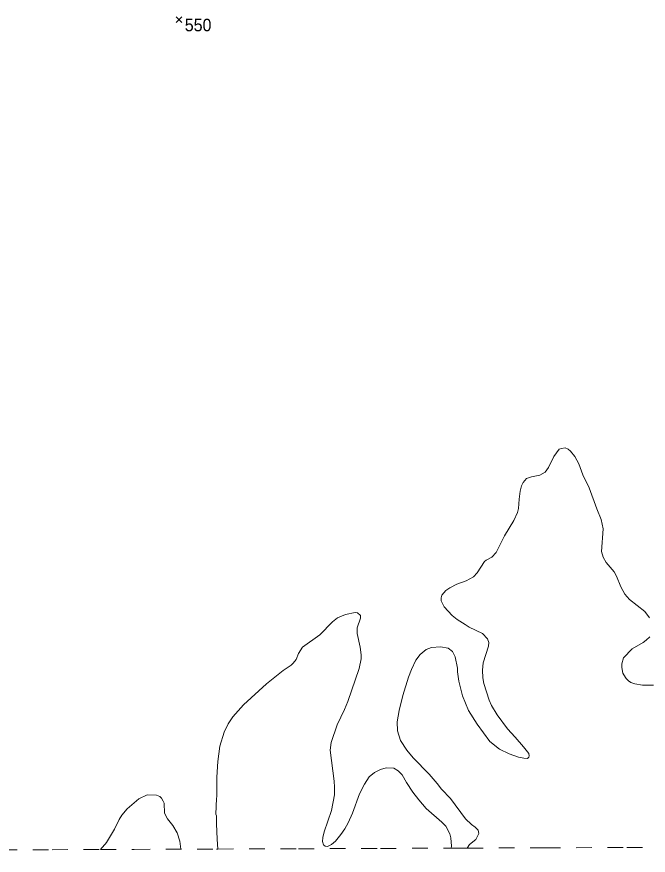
# Model space of a CAD drawing. Extents: x 423 to 448.8, y 7456.3 to 7484.
# Drawn here: x 439.12 to 443.14, y 7456.29 to 7461.63 of the extents above; entities that cross this region are included whole.
import ezdxf
from ezdxf.enums import TextEntityAlignment as Align

# ---------------------------------------------------------------- set-up
doc = ezdxf.new("R2010")
doc.units = 0
doc.header["$LTSCALE"] = 0.032
doc.linetypes.add('SHORT_DASHED', pattern=[2.7, 1.5, -1.2])
for name, color, linetype, lineweight in [('2', 7, 'Continuous', 13), ('21', 7, 'Continuous', 25), ('22', 7, 'SHORT_DASHED', 13)]:
    doc.layers.add(name, color=color, linetype=linetype, lineweight=lineweight)
doc.layers.add('61', color=7, linetype='Continuous')

msp = doc.modelspace()

# ---------------------------------------------------------------- linework, layer by layer
at = {"layer": '2'}
for points in [[(443.1494, 7457.8027), (443.1192, 7457.8422), (443.0202, 7457.9187), (442.9916, 7457.952), (442.9669, 7457.9984), (442.9383, 7458.0665), (442.9228, 7458.0943), (442.8725, 7458.1538), (442.8532, 7458.1887), (442.8439, 7458.2243), (442.8532, 7458.3681), (442.8408, 7458.4284), (442.8122, 7458.4965), (442.765, 7458.6295), (442.7248, 7458.7131), (442.6985, 7458.7827), (442.673, 7458.8306), (442.6459, 7458.8646), (442.6304, 7458.877), (442.6119, 7458.884), (442.5872, 7458.8817), (442.5732, 7458.8755), (442.5399, 7458.8306), (442.5059, 7458.7595), (442.485, 7458.7301), (442.451, 7458.7107), (442.3961, 7458.6999), (442.3659, 7458.6899), (442.3443, 7458.6651), (442.3327, 7458.6419), (442.3249, 7458.6079), (442.318, 7458.5584), (442.3141, 7458.4981), (442.3079, 7458.4733), (442.284, 7458.4222), (442.2251, 7458.3248), (442.1718, 7458.2181), (442.1439, 7458.1887), (442.1092, 7458.1701), (442.0967, 7458.16), (442.0511, 7458.0881), (442.0272, 7458.0626), (441.9808, 7458.0378), (441.9219, 7458.0162), (441.8763, 7457.9938), (441.8524, 7457.9767), (441.826, 7457.9473), (441.8214, 7457.9303), (441.8214, 7457.9094), (441.84, 7457.8723), (441.891, 7457.8166), (441.9243, 7457.7911), (441.9738, 7457.7602), (441.9993, 7457.7431), (442.0844, 7457.7014), (442.1176, 7457.6674), (442.1254, 7457.6442), (442.1231, 7457.621), (442.089, 7457.5158)], [(440.3989, 7456.3287), (440.3959, 7456.3912), (440.3897, 7456.4902), (440.3905, 7456.5397), (440.3866, 7456.552), (440.3905, 7456.651), (440.3936, 7456.6634), (440.3936, 7456.7872), (440.3998, 7456.8862), (440.4129, 7456.9852), (440.4392, 7457.0733), (440.4647, 7457.1259), (440.4949, 7457.1715), (440.5622, 7457.2474), (440.7092, 7457.3811), (440.8159, 7457.4655), (440.8662, 7457.5003), (440.8793, 7457.5134), (440.8971, 7457.5374), (440.9134, 7457.5745), (440.9381, 7457.614), (441.0479, 7457.6937), (441.1292, 7457.7764), (441.1624, 7457.8011), (441.2119, 7457.8236), (441.2738, 7457.8367), (441.2892, 7457.8329), (441.307, 7457.8166), (441.307, 7457.8004), (441.2877, 7457.7385), (441.2869, 7457.7014), (441.3063, 7457.6148), (441.3125, 7457.5653), (441.3125, 7457.5405), (441.3001, 7457.4786), (441.2266, 7457.2683), (441.2065, 7457.2188), (441.1593, 7457.1198), (441.1207, 7457.0084), (441.1145, 7456.9589), (441.1392, 7456.7609), (441.1423, 7456.7237), (441.1415, 7456.6742), (441.123, 7456.5752), (441.0758, 7456.4391), (441.0673, 7456.402), (441.0665, 7456.3772), (441.0719, 7456.3548), (441.082, 7456.347), (441.0974, 7456.3455), (441.1238, 7456.3586), (441.1493, 7456.3795), (441.1833, 7456.4205), (441.2073, 7456.4577), (441.229, 7456.4948), (441.2575, 7456.5567), (441.3017, 7456.6804), (441.3326, 7456.7423), (441.3635, 7456.7879), (441.3976, 7456.8157), (441.4347, 7456.8359), (441.4718, 7456.8459), (441.5205, 7456.8436), (441.5476, 7456.8273), (441.5739, 7456.8026), (441.601, 7456.7531), (441.6412, 7456.6913), (441.6791, 7456.6418), (441.7271, 7456.5868), (441.8261, 7456.5009), (441.8523, 7456.4747), (441.8771, 7456.4252), (441.884, 7456.4004), (441.8879, 7456.3478), (441.885, 7456.3345)], [(443.175, 7457.3719), (443.1038, 7457.3734), (443.0559, 7457.3804), (443.0303, 7457.3897), (443.0149, 7457.4005), (443.0001, 7457.4144), (442.9847, 7457.4384), (442.9793, 7457.4492), (442.9723, 7457.4848), (442.9731, 7457.508), (442.9839, 7457.5474), (443.0373, 7457.6054), (443.1085, 7457.6449), (443.1278, 7457.6588), (443.1502, 7457.6813)], [(442.089, 7457.5158), (442.0844, 7457.4678), (442.0867, 7457.4199), (442.0944, 7457.3843), (442.1277, 7457.2775), (442.1432, 7457.2435), (442.178, 7457.1832), (442.2445, 7457.095), (442.294, 7457.0416), (442.3466, 7456.9797), (442.3713, 7456.9484), (442.3791, 7456.938), (442.3829, 7456.9217), (442.3806, 7456.9132), (442.3713, 7456.9055), (442.3489, 7456.907), (442.3141, 7456.9148), (442.2546, 7456.9357), (442.1934, 7456.9658), (442.1323, 7457.0138), (442.0503, 7457.1244), (441.9954, 7457.211), (441.9583, 7457.3054), (441.9343, 7457.3982), (441.9258, 7457.4585), (441.9258, 7457.4817), (441.9103, 7457.5529), (441.8941, 7457.5869), (441.867, 7457.6086), (441.8183, 7457.6179), (441.7596, 7457.6124), (441.7255, 7457.5993), (441.6884, 7457.5676), (441.6605, 7457.5328), (441.6327, 7457.4724), (441.6141, 7457.4245), (441.577, 7457.3069), (441.5538, 7457.211), (441.5414, 7457.1399), (441.543, 7457.0811), (441.5631, 7457.0207), (441.6033, 7456.9589), (441.6427, 7456.9109), (441.7448, 7456.8057), (441.7967, 7456.7469), (441.823, 7456.7113), (441.8802, 7456.6502), (441.9761, 7456.5218), (442.0148, 7456.4855), (442.0387, 7456.4685), (442.0573, 7456.4483), (442.0612, 7456.4282), (442.0426, 7456.3904), (442.0024, 7456.3579), (441.9882, 7456.3349)], [(440.1639, 7456.3278), (440.1577, 7456.3795), (440.1407, 7456.4314), (440.1136, 7456.4778), (440.078, 7456.5211), (440.0595, 7456.5574), (440.0564, 7456.6201), (440.0502, 7456.634), (440.0394, 7456.6533), (440.0293, 7456.6626), (440.0092, 7456.6727), (439.9497, 7456.6734), (439.8955, 7456.6495), (439.822, 7456.5852), (439.788, 7456.5443), (439.7702, 7456.5165), (439.7416, 7456.4561), (439.6905, 7456.3702), (439.6812, 7456.3594), (439.6612, 7456.3369), (439.6511, 7456.3257)]]:
    msp.add_lwpolyline(points, dxfattribs=at)
at = {"layer": '21'}
for p, q in [((440.133, 7461.6313), (440.1705, 7461.5938)), ((440.1705, 7461.6313), (440.133, 7461.5938))]:
    msp.add_line(p, q, dxfattribs=at)
at = {"layer": '22'}
for points in [[(440.3989, 7456.3287), (440.9131, 7456.3308), (441.436, 7456.3328), (441.885, 7456.3345)], [(441.885, 7456.3345), (441.9589, 7456.3348), (441.9882, 7456.3349)], [(441.9882, 7456.3349), (442.4818, 7456.3368), (443.0047, 7456.3388), (443.5276, 7456.3408), (443.7955, 7456.3418), (443.9272, 7456.3423)], [(431.1993, 7456.2894), (431.5007, 7456.2908), (432.0236, 7456.2932), (432.5465, 7456.2955), (433.0694, 7456.2979), (433.5924, 7456.3002), (434.1153, 7456.3025), (434.6382, 7456.3048), (435.1611, 7456.307), (435.684, 7456.3093), (436.2069, 7456.3115), (436.7298, 7456.3137), (437.2527, 7456.3159), (437.7756, 7456.3181), (438.2985, 7456.3203), (438.8214, 7456.3224), (439.3443, 7456.3245), (439.6511, 7456.3257)], [(439.6511, 7456.3257), (439.8673, 7456.3266), (440.3902, 7456.3287), (440.3989, 7456.3287)]]:
    msp.add_lwpolyline(points, dxfattribs=at)

# ---------------------------------------------------------------- texts
at = {"layer": '61', "width": 0.95}
msp.add_text('550', height=0.08, dxfattribs=at).set_placement((440.2736, 7461.5387), align=Align.CENTER)

doc.saveas('drawing.dxf')
